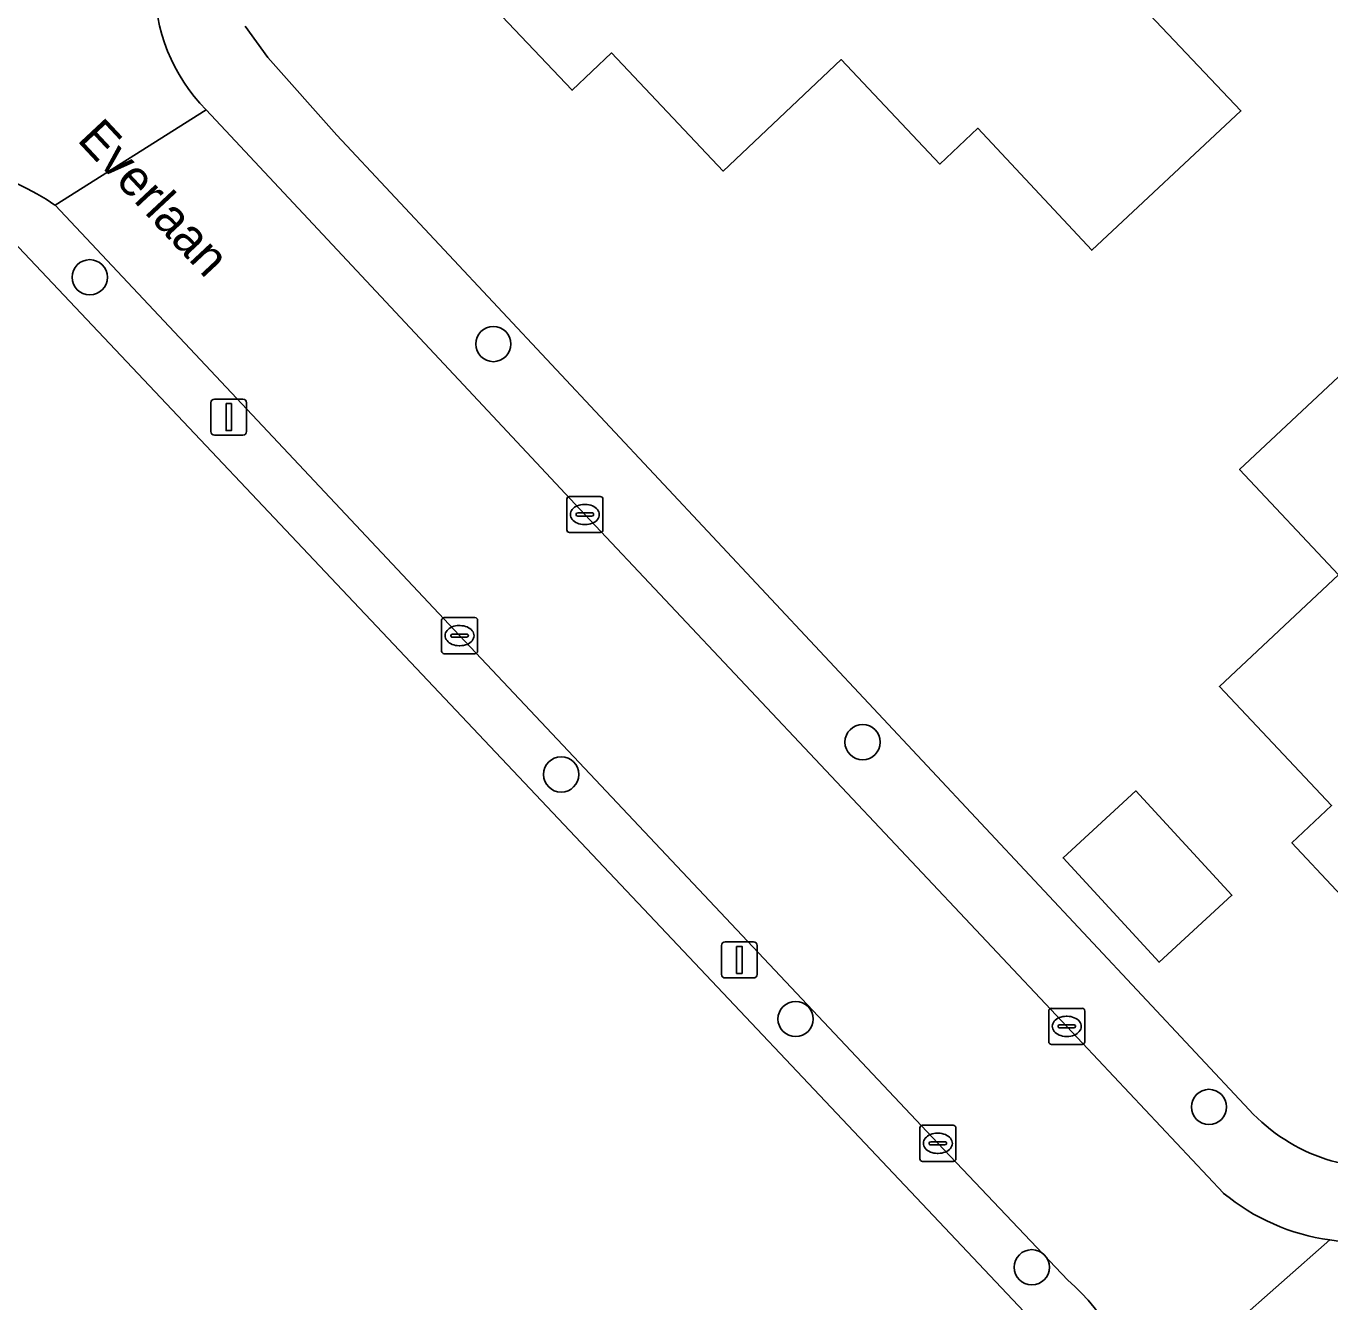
# Model space of a CAD drawing. Extents: x 162661 to 163484, y 380247 to 381230.
# Drawn here: x 163330.18 to 163366.35, y 380813.89 to 380849.27 of the extents above; entities that cross this region are included whole.
import ezdxf

# ---------------------------------------------------------------- set-up
doc = ezdxf.new("R2010")
doc.units = 0
for name, color, linetype in [('IMGEO_Boom', 7, 'Continuous'), ('IMGEO_Erf', 7, 'Continuous'), ('IMGEO_Groenvoorziening', 7, 'Continuous'), ('IMGEO_Kolk', 7, 'Continuous'), ('IMGEO_Lichtmast', 7, 'Continuous'), ('IMGEO_Openbare_ruimte_label', 7, 'Continuous'), ('IMGEO_Pand', 7, 'Continuous'), ('IMGEO_Rijbaan_lokaal_gesloten', 7, 'Continuous')]:
    doc.layers.add(name, color=color, linetype=linetype)

msp = doc.modelspace()

# ---------------------------------------------------------------- linework, layer by layer
at = {"layer": 'IMGEO_Boom'}
for centre in [(163331.943, 380842.306), (163343.14, 380840.455), (163353.384, 380829.415), (163345.022, 380828.519), (163351.525, 380821.737), (163362.994, 380819.298), (163358.079, 380814.852)]:
    msp.add_circle(centre, 0.489, dxfattribs=at)
at = {"layer": 'IMGEO_Erf'}
for points in [[(163363.882, 380846.918), (163359.74, 380843.055), (163356.584, 380846.44), (163355.528, 380845.443), (163352.791, 380848.343), (163349.513, 380845.249), (163346.419, 380848.527), (163345.322, 380847.491), (163342.852, 380850.109), (163343.953, 380851.135), (163343.269, 380851.862), (163346.634, 380855.024), (163347.281, 380854.326), (163349.833, 380856.699), (163352.921, 380853.428), (163355.466, 380855.831), (163360.682, 380850.307)], [(163374.252, 380836.273), (163371.689, 380833.87), (163374.775, 380830.595), (163372.226, 380828.194), (163372.906, 380827.461), (163369.535, 380824.303), (163368.86, 380825.037), (163367.75, 380824.002), (163365.294, 380826.621), (163366.396, 380827.654), (163363.283, 380830.957), (163366.584, 380834.052), (163363.845, 380836.972), (163369.036, 380841.838)], [(163360.968, 380828.064), (163363.629, 380825.17), (163361.609, 380823.312), (163358.948, 380826.205)]]:
    msp.add_lwpolyline(points, close=True, dxfattribs=at)
for points in [[(163336.256, 380849.272), (163336.881, 380848.403), (163338.801, 380846.249), (163364.11, 380819.217)], [(163358.343, 380813.122), (163328.383, 380844.802), (163327.309, 380843.958), (163315.112, 380834.375), (163312.188, 380832.112), (163296.843, 380820.233), (163294.076, 380818.108), (163289.632, 380814.871), (163286.499, 380812.86), (163283.372, 380810.85), (163278.115, 380807.338)]]:
    msp.add_lwpolyline(points, dxfattribs=at)
msp.add_arc((163367.791, 380822.615), 5.01, 222.7073, 281.1708, dxfattribs=at)
at = {"layer": 'IMGEO_Groenvoorziening'}
for points in [[(163364.11, 380819.217), (163338.801, 380846.249), (163336.881, 380848.403), (163336.256, 380849.272)], [(163335.169, 380846.951), (163345.679, 380835.728), (163359.049, 380821.533), (163363.393, 380816.911)], [(163322.625, 380843.354), (163323.72, 380842.014), (163326.824, 380844.551), (163327.309, 380843.958), (163328.383, 380844.802), (163358.343, 380813.122)], [(163359.075, 380814.491), (163355.473, 380818.29), (163342.204, 380832.368), (163330.978, 380844.305)]]:
    msp.add_lwpolyline(points, dxfattribs=at)
for centre, radius, start, end in [((163338.712, 380850.437), 4.97, 134.1, 224.5357), ((163327.339, 380839.107), 6.345, 55.0065, 137.984), ((163367.791, 380822.615), 5.01, 222.7073, 281.1708), ((163367.155, 380821.459), 5.904, 262.1668, 314.5292), ((163367.156, 380821.454), 5.899, 230.3598, 262.1438), ((163355.525, 380810.306), 5.488, 5.9608, 49.6895)]:
    msp.add_arc(centre, radius, start, end, dxfattribs=at)
at = {"layer": 'IMGEO_Kolk'}
for p, q in [((163345.178, 380835.302), (163345.178, 380836.154)), ((163345.253, 380836.228), (163346.105, 380836.228)), ((163346.179, 380836.154), (163346.179, 380835.302)), ((163345.437, 380835.722), (163345.437, 380835.734)), ((163345.48, 380835.771), (163345.878, 380835.771)), ((163345.666, 380836.008), (163345.691, 380836.008)), ((163345.921, 380835.734), (163345.921, 380835.722)), ((163345.875, 380835.685), (163345.477, 380835.685)), ((163345.689, 380835.448), (163345.664, 380835.448)), ((163346.105, 380835.228), (163345.253, 380835.228)), ((163341.778, 380832.868), (163342.63, 380832.868)), ((163341.703, 380831.942), (163341.703, 380832.794)), ((163342.191, 380832.648), (163342.216, 380832.648)), ((163342.704, 380832.794), (163342.704, 380831.942)), ((163341.962, 380832.362), (163341.962, 380832.374)), ((163342.4, 380832.325), (163342.002, 380832.325)), ((163342.005, 380832.411), (163342.403, 380832.411)), ((163342.446, 380832.374), (163342.446, 380832.362)), ((163342.63, 380831.868), (163341.778, 380831.868)), ((163342.214, 380832.088), (163342.189, 380832.088)), ((163358.623, 380822.033), (163359.475, 380822.033)), ((163358.548, 380821.107), (163358.548, 380821.959)), ((163359.036, 380821.813), (163359.061, 380821.813)), ((163359.549, 380821.959), (163359.549, 380821.107)), ((163358.807, 380821.527), (163358.807, 380821.539)), ((163359.245, 380821.49), (163358.847, 380821.49)), ((163358.85, 380821.576), (163359.248, 380821.576)), ((163359.291, 380821.539), (163359.291, 380821.527)), ((163359.475, 380821.033), (163358.623, 380821.033)), ((163359.059, 380821.253), (163359.034, 380821.253)), ((163355.047, 380818.79), (163355.899, 380818.79)), ((163354.972, 380817.864), (163354.972, 380818.716)), ((163355.46, 380818.57), (163355.485, 380818.57)), ((163355.973, 380818.716), (163355.973, 380817.864)), ((163355.231, 380818.284), (163355.231, 380818.296)), ((163355.669, 380818.247), (163355.271, 380818.247)), ((163355.274, 380818.333), (163355.672, 380818.333)), ((163355.483, 380818.01), (163355.458, 380818.01)), ((163355.715, 380818.296), (163355.715, 380818.284)), ((163355.899, 380817.79), (163355.047, 380817.79))]:
    msp.add_line(p, q, dxfattribs=at)
for points in [[(163345.178, 380835.302), (163345.178, 380836.154)], [(163345.253, 380836.228), (163346.105, 380836.228)], [(163346.179, 380836.154), (163346.179, 380835.302)], [(163346.105, 380835.228), (163345.253, 380835.228)], [(163341.778, 380832.868), (163342.63, 380832.868)], [(163341.703, 380831.942), (163341.703, 380832.794)], [(163342.704, 380832.794), (163342.704, 380831.942)], [(163342.63, 380831.868), (163341.778, 380831.868)], [(163358.623, 380822.033), (163359.475, 380822.033)], [(163358.548, 380821.107), (163358.548, 380821.959)], [(163359.549, 380821.959), (163359.549, 380821.107)], [(163359.475, 380821.033), (163358.623, 380821.033)], [(163355.047, 380818.79), (163355.899, 380818.79)], [(163354.972, 380817.864), (163354.972, 380818.716)], [(163355.973, 380818.716), (163355.973, 380817.864)], [(163355.899, 380817.79), (163355.047, 380817.79)]]:
    msp.add_lwpolyline(points, dxfattribs=at)
for centre, radius, start, end in [((163345.255, 380836.152), 0.0765, 91.552, 178.448), ((163345.255, 380836.152), 0.0765, 91.552, 178.448), ((163346.103, 380836.152), 0.0765, 1.552, 88.448), ((163346.103, 380836.152), 0.0765, 1.552, 88.448), ((163345.477, 380835.731), 0.0403, 85.8775, 175.7526), ((163345.882, 380835.733), 0.0386, 1.7309, 96.639), ((163345.474, 380835.721), 0.0366, 178.938, 274.7102), ((163345.878, 380835.728), 0.043, 264.8664, 352.4533), ((163345.255, 380835.304), 0.0765, 181.552, 268.448), ((163345.255, 380835.304), 0.0765, 181.552, 268.448), ((163346.103, 380835.304), 0.0765, 271.552, 358.448), ((163346.103, 380835.304), 0.0765, 271.552, 358.448), ((163341.78, 380832.792), 0.0765, 91.552, 178.448), ((163341.78, 380832.792), 0.0765, 91.552, 178.448), ((163342.628, 380832.792), 0.0765, 1.552, 88.448), ((163342.628, 380832.792), 0.0765, 1.552, 88.448), ((163342.002, 380832.371), 0.0403, 85.8775, 175.7526), ((163341.999, 380832.361), 0.0366, 178.938, 274.7102), ((163342.403, 380832.368), 0.043, 264.8664, 352.4533), ((163342.407, 380832.373), 0.0386, 1.7309, 96.639), ((163341.78, 380831.944), 0.0765, 181.552, 268.448), ((163341.78, 380831.944), 0.0765, 181.552, 268.448), ((163342.628, 380831.944), 0.0765, 271.552, 358.448), ((163342.628, 380831.944), 0.0765, 271.552, 358.448), ((163358.625, 380821.957), 0.0765, 91.552, 178.448), ((163358.625, 380821.957), 0.0765, 91.552, 178.448), ((163359.473, 380821.957), 0.0765, 1.552, 88.448), ((163359.473, 380821.957), 0.0765, 1.552, 88.448), ((163358.847, 380821.536), 0.0403, 85.8775, 175.7526), ((163358.844, 380821.526), 0.0366, 178.938, 274.7102), ((163359.248, 380821.533), 0.043, 264.8664, 352.4533), ((163359.252, 380821.538), 0.0386, 1.7309, 96.639), ((163358.625, 380821.109), 0.0765, 181.552, 268.448), ((163358.625, 380821.109), 0.0765, 181.552, 268.448), ((163359.473, 380821.109), 0.0765, 271.552, 358.448), ((163359.473, 380821.109), 0.0765, 271.552, 358.448), ((163355.049, 380818.714), 0.0765, 91.552, 178.448), ((163355.049, 380818.714), 0.0765, 91.552, 178.448), ((163355.897, 380818.714), 0.0765, 1.552, 88.448), ((163355.897, 380818.714), 0.0765, 1.552, 88.448), ((163355.271, 380818.293), 0.0403, 85.8775, 175.7526), ((163355.268, 380818.283), 0.0366, 178.938, 274.7102), ((163355.672, 380818.29), 0.043, 264.8664, 352.4533), ((163355.676, 380818.295), 0.0386, 1.7309, 96.639), ((163355.049, 380817.866), 0.0765, 181.552, 268.448), ((163355.049, 380817.866), 0.0765, 181.552, 268.448), ((163355.897, 380817.866), 0.0765, 271.552, 358.448), ((163355.897, 380817.866), 0.0765, 271.552, 358.448)]:
    msp.add_arc(centre, radius, start, end, dxfattribs=at)
for centre, major_axis, ratio, start_param, end_param in [((163345.665, 380835.728), (-0.387, 0.002), 0.722429, 4.712389, 7.853982), ((163345.69, 380835.728), (-0.39, 0.002), 0.717154, 1.570796, 4.712389), ((163342.19, 380832.368), (-0.387, 0.002), 0.722429, 4.712389, 7.853982), ((163342.215, 380832.368), (-0.39, 0.002), 0.717154, 1.570796, 4.712389), ((163359.035, 380821.533), (-0.387, 0.002), 0.722429, 4.712389, 7.853982), ((163359.06, 380821.533), (-0.39, 0.002), 0.717154, 1.570796, 4.712389), ((163355.459, 380818.29), (-0.387, 0.002), 0.722429, 4.712389, 7.853982), ((163355.484, 380818.29), (-0.39, 0.002), 0.717154, 1.570796, 4.712389)]:
    msp.add_ellipse(centre, major_axis=major_axis, ratio=ratio, start_param=start_param, end_param=end_param, dxfattribs=at)
at = {"layer": 'IMGEO_Lichtmast'}
for p, q in [((163335.303, 380838.029), (163335.303, 380838.829)), ((163335.303, 380838.829), (163335.303, 380838.029)), ((163335.403, 380838.929), (163336.193, 380838.929)), ((163336.193, 380838.929), (163335.403, 380838.929)), ((163336.293, 380838.829), (163336.293, 380838.029)), ((163336.293, 380838.029), (163336.293, 380838.829)), ((163336.193, 380837.929), (163335.403, 380837.929)), ((163335.403, 380837.929), (163336.193, 380837.929)), ((163349.57, 380823.875), (163350.36, 380823.875)), ((163350.36, 380823.875), (163349.57, 380823.875)), ((163349.47, 380822.975), (163349.47, 380823.775)), ((163349.47, 380823.775), (163349.47, 380822.975)), ((163350.46, 380823.775), (163350.46, 380822.975)), ((163350.46, 380822.975), (163350.46, 380823.775)), ((163350.36, 380822.875), (163349.57, 380822.875)), ((163349.57, 380822.875), (163350.36, 380822.875))]:
    msp.add_line(p, q, dxfattribs=at)
for points in [[(163335.723, 380838.804), (163335.873, 380838.804), (163335.873, 380838.054), (163335.723, 380838.054), (163335.723, 380838.804)], [(163349.89, 380823.75), (163350.04, 380823.75), (163350.04, 380823), (163349.89, 380823), (163349.89, 380823.75)]]:
    msp.add_lwpolyline(points, dxfattribs=at)
for centre, start, end in [((163335.403, 380838.829), 90, 180), ((163335.403, 380838.829), 90, 180), ((163336.193, 380838.829), 0, 90), ((163336.193, 380838.829), 360, 90), ((163335.403, 380838.029), 180, 270), ((163335.403, 380838.029), 180, 270), ((163336.193, 380838.029), 270, 0), ((163336.193, 380838.029), 270, 0), ((163349.57, 380823.775), 90, 180), ((163349.57, 380823.775), 90, 180), ((163350.36, 380823.775), 0, 90), ((163350.36, 380823.775), 360, 90), ((163349.57, 380822.975), 180, 270), ((163349.57, 380822.975), 180, 270), ((163350.36, 380822.975), 270, 0), ((163350.36, 380822.975), 270, 0)]:
    msp.add_arc(centre, 0.1, start, end, dxfattribs=at)
at = {"layer": 'IMGEO_Pand'}
for points in [[(163355.466, 380855.831), (163352.921, 380853.428), (163349.833, 380856.699), (163347.281, 380854.326), (163346.634, 380855.024), (163343.269, 380851.862), (163343.953, 380851.135), (163342.852, 380850.109), (163345.322, 380847.491), (163346.419, 380848.527), (163349.513, 380845.249), (163352.791, 380848.343), (163355.528, 380845.443), (163356.584, 380846.44), (163359.74, 380843.055), (163363.882, 380846.918), (163360.682, 380850.307)], [(163374.775, 380830.595), (163371.689, 380833.87), (163374.252, 380836.273), (163369.036, 380841.838), (163363.845, 380836.972), (163366.584, 380834.052), (163363.283, 380830.957), (163366.396, 380827.654), (163365.294, 380826.621), (163367.75, 380824.002), (163368.86, 380825.037), (163369.535, 380824.303), (163372.906, 380827.461), (163372.226, 380828.194)], [(163358.948, 380826.205), (163361.609, 380823.312), (163363.629, 380825.17), (163360.968, 380828.064)]]:
    msp.add_lwpolyline(points, close=True, dxfattribs=at)
at = {"layer": 'IMGEO_Rijbaan_lokaal_gesloten'}
for points in [[(163330.978, 380844.305), (163335.169, 380846.951)], [(163345.679, 380835.728), (163335.169, 380846.951), (163330.978, 380844.305), (163342.204, 380832.368), (163355.473, 380818.29), (163359.075, 380814.491)], [(163363.393, 380816.911), (163359.049, 380821.533), (163345.679, 380835.728)], [(163360.983, 380810.876), (163366.35, 380815.61)], [(163366.35, 380815.61), (163360.983, 380810.876)]]:
    msp.add_lwpolyline(points, dxfattribs=at)
for centre, radius, start, end in [((163338.712, 380850.437), 4.97, 134.1, 224.5357), ((163327.339, 380839.107), 6.345, 55.0065, 137.984), ((163367.155, 380821.459), 5.904, 262.1668, 314.5292), ((163367.156, 380821.454), 5.899, 230.3598, 262.1438), ((163355.525, 380810.306), 5.488, 5.9608, 49.6895)]:
    msp.add_arc(centre, radius, start, end, dxfattribs=at)

# ---------------------------------------------------------------- texts
at = {"layer": 'IMGEO_Openbare_ruimte_label'}
msp.add_text('Everlaan', height=1, rotation=313.0558, dxfattribs=at).set_placement((163331.566, 380846.106))

doc.saveas('drawing.dxf')
